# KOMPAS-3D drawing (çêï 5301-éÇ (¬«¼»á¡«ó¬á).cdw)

Referenced files in C:\Вороровано\Мои документы\: Лист Зил 5301.cdw
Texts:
  ЗИЛ 5301-ВА (компановка)
  133 1 134 1 135 1 136 0 50 1|SPDS|133 1 134 1 135 1 136 0 50 1
  125 1 126 1 127 1 128 0 50 1|SPDS|125 1 126 1 127 1 128 0 50 1
  129 1 130 1 131 1 132 0 50 1|SPDS|129 1 130 1 131 1 132 0 50 1
  Техническая характеристика ЗИЛ 5301-ВА.
  Symbol type A
  1.Грузоподъёмность, кг---------------------------------2125+225
  2. Полная масса, кг----------------------------------------8649
  В том числе
  на переднюю ось----------------------------------358
  на задний мост-----------------------------------730
  3. Максимальная скорость
  движеня, км/ч--------------------------------------------100
  4. Двигатель-----------------------------------------Д-245.12.1.
  5. Максимальный крутящий
  момент двигателя при
  1433 об/мин, Нxм-----------------------------------------484
  6. Номинальная мощность при
  2484 об/мин, КВт----------------------------------------112
  7. Контрольный расход
  топлива, л/100км
  при 60 км/ч----------------------------------12
  при 80 км/ч----------------------------------17
  8. Передаточные числа КПП
  II-------------------------------4,815
  III-------------------------------2,851
  IV-------------------------------1,689
  9. Шины--------------------------------------------21/75 R 17.5
  ЗИЛ 5301-ВА
  (компановка)
  www.4ertim.com-
Dimensions and other numbers on the sheet: 4250; 1820; 550; 6818; 820; 1934; 3130; 2195; 1409; 924; 2100; 4307; 1100; 767; 359; 2914; 1599; 2700; 4467; 170; 3060; 1190; 213; 2180; 1230; 1690; 1:15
